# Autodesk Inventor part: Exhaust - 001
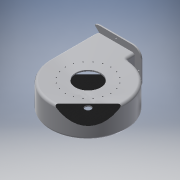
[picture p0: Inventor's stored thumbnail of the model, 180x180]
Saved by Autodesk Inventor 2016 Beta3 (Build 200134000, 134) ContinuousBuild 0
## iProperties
Created: 2006-05
Part Number: Exhaust - 001
Document SubType Name: Modeling
Designer: Autodesk, Inc.
Density: 2.71 g/cm^3
Material: Aluminum-6061
Mass: 27045.4 g
Surface Area: 19920.1 cm^2
Volume: 9979.84 cm^3
Appearance: Aluminum - Flat
Author: Autodesk, Inc.
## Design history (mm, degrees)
derived "MainGeom.ipt"
sketch "Sketch1" dims "d42" = 600
  geometry: L1 (0, 370)-(-300, 370); L2 (-300, 0)-(-300, 370); L3 (-200, 0)-(-200, -350); L4 (-200, -350)-(200, -350); L5 (200, -350)-(200, 0); L6 (0, 370)-(0, 300); C1 r 100 at (0, 0); C2 r 25 at (0, 0); A1 r 200 centre (0, 0) between (200, 0) and (-200, 0); 2 further points
  constraints: 12 end point, 3 centre point, 3 vertical, 2 horizontal, 2 point on circle, 2 point on line, 1 coincident, 5 other
  dimensions: "d41" = 50 diameter of C2; "d43" = 200 radius of A1; "d44" = 200 diameter of C1; "d45" = 350 distance from line of L4 point (0, 0); "d46" = 370 distance from line of L1 point (0, 0)
extrude "Extrusion1" new body sketch "Sketch1" distance "d1" = 200; taper "d2" = 0 deg
fillet "Fillet1" dims "d37" = 20
sketch "Sketch12"
  geometry: L1 (-20, -20)-(-20, -180) reference; L2 (0, -200)-(260, -200) reference; L3 (280, -20)-(280, -180) reference; L4 (260, 0)-(0, 0) reference; L5 (-70, -20)-(-70, -180); L6 (0, -250)-(260, -250); L7 (330, -180)-(330, -20); L8 (260, 50)-(0, 50); L9 (-50, -20)-(-50, -180); L10 (0, -230)-(260, -230); L11 (310, -180)-(310, -20); L12 (260, 30)-(0, 30); C1 r 6.35 at (130, 30); C2 r 6.35 at (-50, -100); C3 r 6.35 at (130, -230); C4 r 6.35 at (310, -100); A1 r 20 centre (0, -20) between (0, 0) and (-20, -20) reference; A2 r 20 centre (0, -180) between (-20, -180) and (0, -200) reference; A3 r 20 centre (260, -180) between (260, -200) and (280, -180) reference; A4 r 20 centre (260, -20) between (280, -20) and (260, 0) reference; A5 r 70 centre (0, -20) between (0, 50) and (-70, -20); A6 r 70 centre (0, -180) between (-70, -180) and (0, -250); A7 r 70 centre (260, -180) between (260, -250) and (330, -180); A8 r 70 centre (260, -20) between (330, -20) and (260, 50); A9 r 50 centre (0, -20) between (0, 30) and (-50, -20); A10 r 50 centre (0, -180) between (-50, -180) and (0, -230); A11 r 50 centre (260, -180) between (260, -230) and (310, -180); A12 r 50 centre (260, -20) between (310, -20) and (260, 30); 5 further points
  constraints: 16 end point, 16 point on circle, 12 centre point, 4 coincident, 4 midpoint, 3 equal radius, 14 other
  dimensions: "d54" = 50 distance between parallel lines of L8 L4; "d55" = 30 distance between parallel lines of L4 L12; "d58" = 400 distance between parallel lines of L7 L5 (derived); "d59" = 300 distance between parallel lines of L6 L8 (derived); "d60" = 12.7 diameter of C3
  node "Projected Loop2"
extrude "Extrusion8" join sketch "Sketch12" distance "d47" = 10.16 (= Thickness); taper "d48" = 0 deg
shell "Shell1" dims "d17" = 10.16 (= Thickness)
extrude "Extrusion4" cut sketch "Sketch1" stored distance "d18" = 100; taper "d19" = 0 deg
extrude "Extrusion9" cut sketch "Sketch1" stored distance "d49" = 10.16 (= Thickness); taper "d50" = 0 deg
sketch "Sketch8" dims "d26" = 360
  geometry: 3 further points
  constraints: 2 vertical alignment, 1 coincident, 2 other
hole "Hole1" sketch "Sketch8" at (280, -190) diameter "d27" = 7.7978; stored, may be unused: countersink angle "d31" = 90 deg, drill point angle "d33" = 118 deg; dims "d28" = 6, "d29" = 4, "d30" = 2, "d32" = 8
extrude "Extrusion10" cut sketch "Sketch12" stored distance "d56" = 10.16 (= Thickness); taper "d57" = 0 deg
body "Solid1"
pattern_circular "Circular Pattern2" dims angle "d52" = 360 deg
other parameters: "Thickness" = 10.16 [user parameter; used in 4 equation terms]
